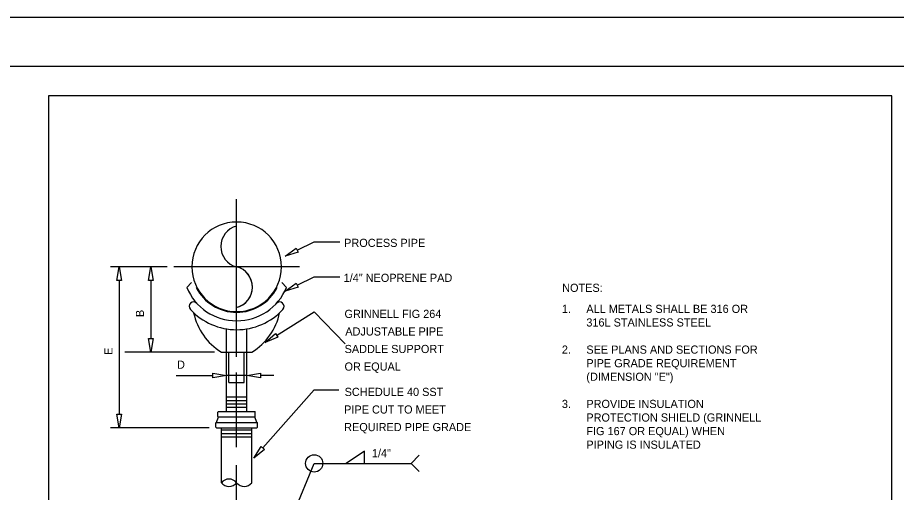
# Model space of a CAD drawing. Extents: x 2147138 to 2147698, y 2147153 to 2147515.
# Drawn here: x 2147293.3 to 2147422.8, y 2147445.1 to 2147515.1 of the extents above; entities that cross this region are included whole.
import ezdxf

# ---------------------------------------------------------------- set-up
doc = ezdxf.new("R2010")
doc.units = 0
for name, color, linetype in [('CONSTRUCTION_CLASS', 7, 'Continuous'), ('D-PIPE-CNTR', 7, 'Continuous'), ('D-PIPE-HDLN', 7, 'Continuous'), ('G-ANNO-TEXT-LW10', 7, 'Continuous'), ('G-DETL-ANNO-LW10', 7, 'Continuous'), ('G-DETL-LW10', 7, 'Continuous'), ('G-DETL-LW20', 7, 'Continuous'), ('G-DETL-PATT', 7, 'Continuous'), ('PATTERN_CLASS', 7, 'Continuous')]:
    doc.layers.add(name, color=color, linetype=linetype)

msp = doc.modelspace()

# ---------------------------------------------------------------- linework, layer by layer
at = {"layer": 'CONSTRUCTION_CLASS'}
for p, q in [((2147697.66, 2147515.08), (2147137.79, 2147515.08)), ((2147160.2, 2147507.94), (2147689.06, 2147507.94))]:
    msp.add_line(p, q, dxfattribs=at)
at = {"layer": 'D-PIPE-CNTR'}
for p, q in [((2147325.59, 2147465.11), (2147325.59, 2147488.31)), ((2147334.83, 2147478.37), (2147316.34, 2147478.37)), ((2147325.59, 2147451.79), (2147325.59, 2147462.79)), ((2147325.59, 2147440.58), (2147325.59, 2147449.16))]:
    msp.add_line(p, q, dxfattribs=at)
at = {"layer": 'D-PIPE-HDLN'}
for p, q in [((2147324.46, 2147461.31), (2147324.46, 2147465.81)), ((2147326.71, 2147461.31), (2147326.71, 2147465.81)), ((2147324.46, 2147461.31), (2147326.71, 2147461.31))]:
    msp.add_line(p, q, dxfattribs=at)
at = {"layer": 'G-ANNO-TEXT-LW10'}
for p, q in [((2147334.51, 2147480.84), (2147337.01, 2147482.07)), ((2147337.01, 2147482.07), (2147340.79, 2147482.07)), ((2147309.9, 2147478.37), (2147307.02, 2147478.37)), ((2147315.24, 2147478.37), (2147309.13, 2147478.37)), ((2147315.34, 2147478.37), (2147311.67, 2147478.37)), ((2147334.51, 2147475.68), (2147337.01, 2147476.91)), ((2147337.01, 2147476.91), (2147340.79, 2147476.91)), ((2147308.3, 2147476.37), (2147308.3, 2147456.66)), ((2147312.95, 2147476.37), (2147312.95, 2147467.81)), ((2147331.47, 2147468.27), (2147337.01, 2147471.75)), ((2147337.01, 2147471.75), (2147341.59, 2147467.03)), ((2147321.81, 2147465.81), (2147309.13, 2147465.81)), ((2147322.34, 2147465.81), (2147311.67, 2147465.81)), ((2147316.67, 2147462.36), (2147322.09, 2147462.36)), ((2147327.09, 2147462.36), (2147324.09, 2147462.36)), ((2147331.09, 2147462.36), (2147329.09, 2147462.36)), ((2147329.44, 2147451.69), (2147337.01, 2147460.26)), ((2147337.01, 2147460.26), (2147340.63, 2147460.26)), ((2147321.54, 2147454.66), (2147307.02, 2147454.66)), ((2147344.44, 2147451.21), (2147341.73, 2147449.42)), ((2147344.44, 2147449.42), (2147344.44, 2147451.21)), ((2147329.28, 2147430.64), (2147337.01, 2147449.42)), ((2147337.01, 2147449.42), (2147340.86, 2147449.42)), ((2147340.86, 2147449.42), (2147351.28, 2147449.42)), ((2147351.28, 2147449.42), (2147352.48, 2147450.61)), ((2147351.28, 2147449.42), (2147352.48, 2147448.23))]:
    msp.add_line(p, q, dxfattribs=at)
for points in [[(2147334.66, 2147480.54), (2147332.72, 2147479.96), (2147334.37, 2147481.14)], [(2147307.96, 2147476.37), (2147308.3, 2147478.37), (2147308.63, 2147476.37)], [(2147312.62, 2147476.37), (2147312.95, 2147478.37), (2147313.29, 2147476.37)], [(2147334.66, 2147475.38), (2147332.72, 2147474.8), (2147334.37, 2147475.98)], [(2147313.29, 2147467.81), (2147312.95, 2147465.81), (2147312.62, 2147467.81)], [(2147331.65, 2147467.99), (2147329.78, 2147467.21), (2147331.29, 2147468.55)], [(2147322.09, 2147462.7), (2147324.09, 2147462.36), (2147322.09, 2147462.03)], [(2147329.09, 2147462.03), (2147327.09, 2147462.36), (2147329.09, 2147462.7)], [(2147308.63, 2147456.66), (2147308.3, 2147454.66), (2147307.96, 2147456.66)], [(2147329.69, 2147451.47), (2147328.12, 2147450.19), (2147329.19, 2147451.91)]]:
    msp.add_lwpolyline(points, close=True, dxfattribs=at)
msp.add_circle((2147337.01, 2147449.42), 1.27, dxfattribs=at)
at = {"layer": 'G-DETL-LW10'}
for p, q in [((2147324.09, 2147459.2), (2147327.09, 2147459.2)), ((2147324.09, 2147458.7), (2147327.09, 2147458.7)), ((2147324.09, 2147458.2), (2147327.09, 2147458.2)), ((2147324.09, 2147457.7), (2147327.09, 2147457.7)), ((2147323.34, 2147454.34), (2147327.84, 2147454.34)), ((2147323.34, 2147453.84), (2147327.84, 2147453.84)), ((2147323.34, 2147453.34), (2147327.84, 2147453.34))]:
    msp.add_line(p, q, dxfattribs=at)
at = {"layer": 'G-DETL-LW20'}
for p, q in [((2147318.24, 2147475.34), (2147318.94, 2147476.05)), ((2147332.94, 2147475.34), (2147332.23, 2147476.05)), ((2147324.09, 2147457.06), (2147324.09, 2147469.23)), ((2147327.09, 2147457.06), (2147327.09, 2147469.23)), ((2147323.34, 2147465.81), (2147327.84, 2147465.81)), ((2147322.62, 2147455.46), (2147322.92, 2147456.26)), ((2147322.84, 2147456.34), (2147322.84, 2147456.98)), ((2147322.92, 2147457.06), (2147328.26, 2147457.06)), ((2147322.92, 2147456.26), (2147328.26, 2147456.26)), ((2147328.56, 2147455.46), (2147328.26, 2147456.26)), ((2147328.34, 2147456.34), (2147328.34, 2147456.98)), ((2147322.54, 2147454.74), (2147322.54, 2147455.38)), ((2147322.62, 2147455.46), (2147328.56, 2147455.46)), ((2147322.62, 2147454.66), (2147328.56, 2147454.66)), ((2147323.34, 2147446.57), (2147323.34, 2147454.66)), ((2147327.84, 2147446.57), (2147327.84, 2147454.66)), ((2147328.64, 2147454.74), (2147328.64, 2147455.38))]:
    msp.add_line(p, q, dxfattribs=at)
for centre, radius, start, end in [((2147325.59, 2147478.37), 6.6, 0, 180), ((2147325.59, 2147478.37), 6.6, 0, 180), ((2147325.59, 2147478.37), 6.6, 180, 0), ((2147325.59, 2147478.37), 7.95, 202.4297, 270), ((2147325.59, 2147478.37), 6.7, 207.2451, 270), ((2147325.59, 2147478.37), 7.95, 270, 337.5703), ((2147325.59, 2147478.37), 6.7, 270, 332.7549), ((2147319.26, 2147472.54), 0.656, 42.6983, 222.6983), ((2147331.91, 2147472.54), 0.656, 317.3017, 137.3017), ((2147325.59, 2147478.37), 9.26, 222.6983, 317.3017), ((2147327.99, 2147473.42), 8.92, 191.7056, 238.5475), ((2147323.18, 2147473.42), 8.92, 301.4525, 348.2944), ((2147322.92, 2147456.98), 0.08, 90, 180), ((2147322.92, 2147456.34), 0.08, 180, 270), ((2147328.26, 2147456.98), 0.08, 0, 90), ((2147328.26, 2147456.34), 0.08, 270, 0), ((2147322.62, 2147455.38), 0.08, 90, 180), ((2147322.62, 2147454.74), 0.08, 180, 270), ((2147328.56, 2147455.38), 0.08, 0, 90), ((2147328.56, 2147454.74), 0.08, 270, 0), ((2147324.46, 2147445.68), 1.43, 38.3518, 141.6482), ((2147324.46, 2147447.46), 1.43, 218.3518, 321.6482), ((2147326.71, 2147447.46), 1.43, 218.3518, 321.6482)]:
    msp.add_arc(centre, radius, start, end, dxfattribs=at)
at = {"layer": 'G-DETL-PATT'}
for points in [[(2147325.59, 2147484.37), (2147325.59, 2147484.97)], [(2147325.59, 2147471.77), (2147325.59, 2147472.39)]]:
    msp.add_lwpolyline(points, dxfattribs=at)
for centre, radius, start, end in [((2147325.59, 2147478.37), 6.6, 90, 270), ((2147326.36, 2147481.37), 3.1, 104.3818, 255.6182), ((2147326.36, 2147481.37), 3.1, 104.3818, 255.6182), ((2147324.82, 2147475.38), 3.09, 283.21, 75.6182), ((2147324.82, 2147475.38), 3.09, 284.3818, 75.6182), ((2147324.46, 2147445.68), 1.43, 38.3518, 141.6482), ((2147324.46, 2147447.46), 1.43, 218.3518, 321.6482)]:
    msp.add_arc(centre, radius, start, end, dxfattribs=at)
at = {"layer": 'PATTERN_CLASS'}
for p, q in [((2147422.07, 2147503.54), (2147297.88, 2147503.54)), ((2147297.88, 2147503.54), (2147297.88, 2147351.27)), ((2147422.07, 2147351.27), (2147422.07, 2147503.54))]:
    msp.add_line(p, q, dxfattribs=at)

# ---------------------------------------------------------------- texts
at = {"layer": 'G-ANNO-TEXT-LW10'}
for s, p in [('PROCESS PIPE', (2147341.42, 2147481.3)), ('1/4" NEOPRENE PAD', (2147341.35, 2147476.15)), ('1.', (2147373.49, 2147471.58)), ('ALL METALS SHALL BE 316 OR ', (2147377.09, 2147471.58)), ('GRINNELL FIG 264', (2147341.47, 2147470.84)), ('316L STAINLESS STEEL', (2147377.09, 2147469.58)), ('ADJUSTABLE PIPE', (2147341.59, 2147468.25)), ('SADDLE SUPPORT', (2147341.49, 2147465.67)), ('2.', (2147373.49, 2147465.58)), ('SEE PLANS AND SECTIONS FOR ', (2147377.09, 2147465.58)), ('D', (2147316.81, 2147463.36)), ('OR EQUAL', (2147341.48, 2147463.08)), ('PIPE GRADE REQUIREMENT ', (2147377.09, 2147463.58)), ('(DIMENSION "E")', (2147377.09, 2147461.58)), ('SCHEDULE 40 SST', (2147341.49, 2147459.35)), ('3.', (2147373.49, 2147457.58)), ('PROVIDE INSULATION ', (2147377.09, 2147457.58)), ('PIPE CUT TO MEET', (2147341.42, 2147456.76)), ('PROTECTION SHIELD (GRINNELL ', (2147377.09, 2147455.58)), ('REQUIRED PIPE GRADE', (2147341.42, 2147454.17)), ('FIG 167 OR EQUAL) WHEN ', (2147377.09, 2147453.58)), ('PIPING IS INSULATED', (2147377.09, 2147451.58)), ('1/4"', (2147345.51, 2147450.32))]:
    msp.add_text(s, height=1.2, dxfattribs=at).set_placement(p)
for s, p in [('B', (2147311.95, 2147470.97)), ('E', (2147307.3, 2147465.4))]:
    msp.add_text(s, height=1.2, rotation=90, dxfattribs=at).set_placement(p)
at = {"layer": 'G-DETL-ANNO-LW10'}
msp.add_text('NOTES:', height=1.2, dxfattribs=at).set_placement((2147373.53, 2147474.68))

doc.saveas('drawing.dxf')
